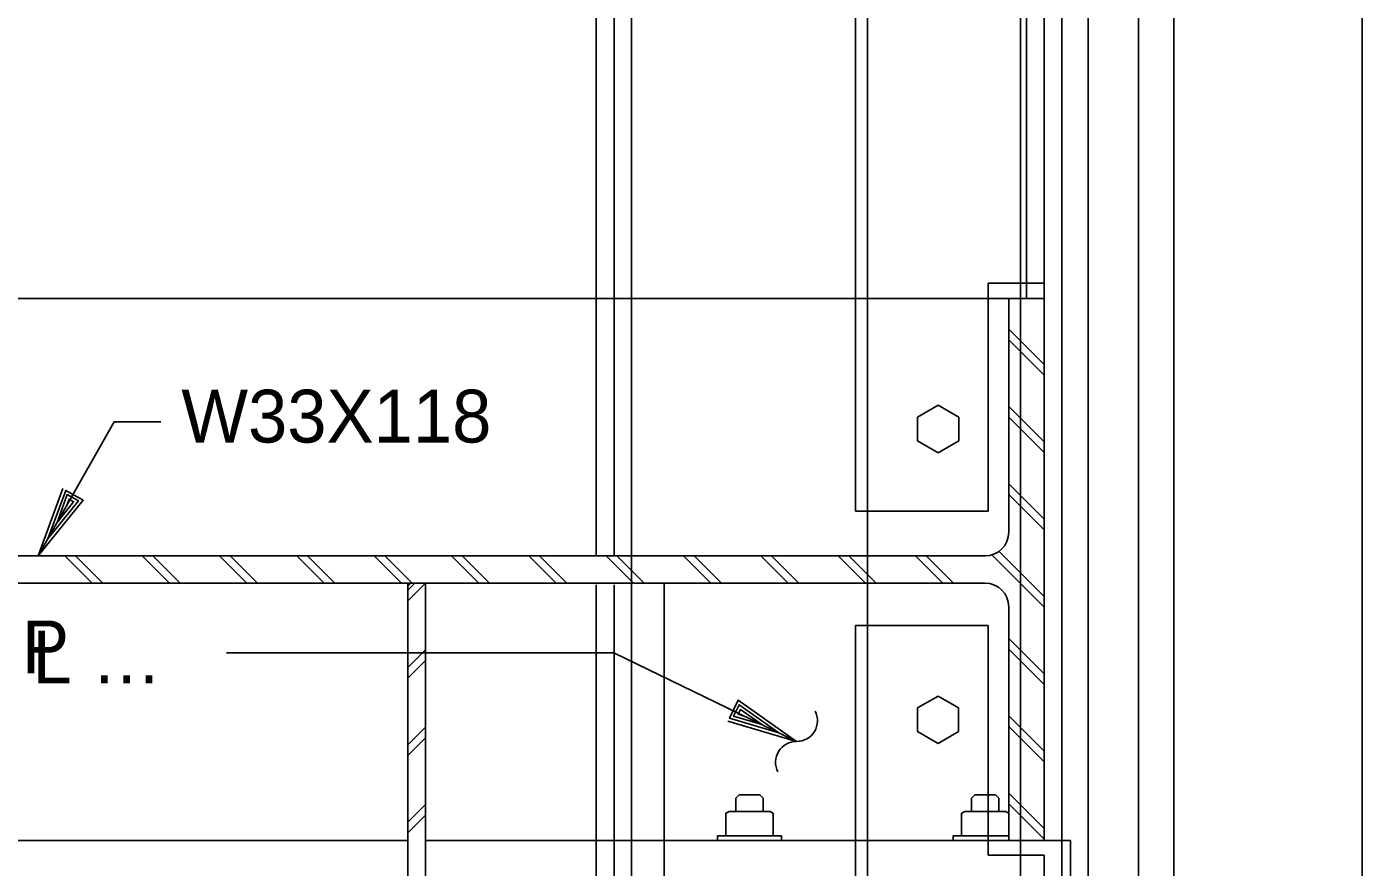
# Model space of a CAD drawing. Extents: x 4.9 to 31.6, y 3.9 to 22.6.
# Drawn here: x 26.163 to 28.524, y 16.518 to 18.004 of the extents above; entities that cross this region are included whole.
import ezdxf

# ---------------------------------------------------------------- set-up
doc = ezdxf.new("R2010")
doc.units = 0
for name, color, linetype in [('Level 2', 7, 'Continuous'), ('Level 25', 7, 'Continuous'), ('Level 3', 7, 'Continuous'), ('Level 44', 7, 'Continuous'), ('Level 50', 7, 'Continuous')]:
    doc.layers.add(name, color=color, linetype=linetype)

msp = doc.modelspace()

# ---------------------------------------------------------------- linework, layer by layer
at = {"layer": 'Level 2'}
for p, q in [((27.9927, 21.2634), (27.9927, 16.5655)), ((28.0395, 21.2634), (28.0395, 15.6699)), ((27.1697, 17.5238), (27.1697, 20.9561)), ((27.201, 17.5238), (27.201, 20.9561)), ((27.2319, 15.7584), (27.2319, 20.9561)), ((27.6281, 17.1475), (27.6281, 20.9561)), ((27.9197, 15.781), (27.9197, 20.6801)), ((27.9302, 17.5238), (27.9302, 20.6801)), ((27.9614, 17.5238), (27.9614, 20.6801)), ((27.9614, 17.5504), (27.8626, 17.5504)), ((27.8626, 17.1475), (27.8626, 17.5504)), ((27.8885, 17.5238), (25.9927, 17.5238)), ((27.1697, 17.0688), (27.1697, 17.5238)), ((27.201, 17.0688), (27.201, 17.5238)), ((27.9614, 17.5238), (27.8885, 17.5238)), ((27.8989, 17.1105), (27.8989, 17.5238)), ((27.9614, 16.5655), (27.9614, 17.5238)), ((27.9614, 17.4071), (27.8989, 17.4696)), ((27.9614, 17.3883), (27.8989, 17.4508)), ((27.7741, 17.3348), (27.7377, 17.3138)), ((27.7741, 17.3348), (27.8104, 17.3138)), ((27.9614, 17.2704), (27.8989, 17.3329)), ((27.7377, 17.3138), (27.7377, 17.272)), ((27.8104, 17.3138), (27.8104, 17.272)), ((27.9614, 17.2516), (27.8989, 17.3141)), ((27.7741, 17.251), (27.7377, 17.272)), ((27.7741, 17.251), (27.8104, 17.272)), ((27.9614, 17.1337), (27.8989, 17.1962)), ((27.9614, 17.1149), (27.8989, 17.1774)), ((27.8626, 17.1475), (27.6281, 17.1475)), ((27.9614, 16.997), (27.8817, 17.0767)), ((25.326, 17.0688), (26.4145, 17.0688)), ((26.2786, 17.0205), (26.2303, 17.0688)), ((26.2974, 17.0205), (26.2491, 17.0688)), ((26.4153, 17.0205), (26.367, 17.0688)), ((26.4342, 17.0205), (26.3858, 17.0688)), ((27.8572, 17.0688), (26.4145, 17.0688)), ((26.552, 17.0205), (26.5037, 17.0688)), ((26.5709, 17.0205), (26.5225, 17.0688)), ((26.6887, 17.0205), (26.6404, 17.0688)), ((26.7076, 17.0205), (26.6592, 17.0688)), ((26.8254, 17.0205), (26.7771, 17.0688)), ((26.8443, 17.0205), (26.7959, 17.0688)), ((26.9621, 17.0205), (26.9138, 17.0688)), ((26.981, 17.0205), (26.9327, 17.0688)), ((27.0988, 17.0205), (27.0505, 17.0688)), ((27.1177, 17.0205), (27.0694, 17.0688)), ((27.2356, 17.0205), (27.1872, 17.0688)), ((27.2544, 17.0205), (27.2061, 17.0688)), ((27.3723, 17.0205), (27.3239, 17.0688)), ((27.3911, 17.0205), (27.3428, 17.0688)), ((27.509, 17.0205), (27.4606, 17.0688)), ((27.5278, 17.0205), (27.4795, 17.0688)), ((27.6457, 17.0205), (27.5973, 17.0688)), ((27.6645, 17.0205), (27.6162, 17.0688)), ((27.7824, 17.0205), (27.7341, 17.0688)), ((27.8012, 17.0205), (27.7529, 17.0688)), ((27.9614, 16.9781), (27.869, 17.0705)), ((25.326, 17.0205), (26.4145, 17.0205)), ((27.8572, 17.0205), (26.4145, 17.0205)), ((26.8364, 15.7168), (26.8364, 17.0205)), ((26.8677, 15.7168), (26.8677, 17.0205)), ((27.1697, 16.5655), (27.1697, 17.0176)), ((27.201, 16.5655), (27.201, 17.0176)), ((27.8989, 16.5655), (27.8989, 16.9788)), ((27.8626, 16.9459), (27.6281, 16.9459)), ((27.6281, 15.781), (27.6281, 16.9459)), ((27.8626, 16.9459), (27.8626, 16.5398)), ((27.9614, 16.8603), (27.8989, 16.9228)), ((27.9614, 16.8415), (27.8989, 16.904)), ((27.7738, 16.8211), (27.7374, 16.8001)), ((27.7738, 16.8211), (27.8101, 16.8001)), ((27.7374, 16.8001), (27.7374, 16.7583)), ((27.8101, 16.8001), (27.8101, 16.7583)), ((27.9614, 16.7236), (27.8989, 16.7861)), ((27.9614, 16.7048), (27.8989, 16.7673)), ((27.7738, 16.7373), (27.7374, 16.7583)), ((27.7738, 16.7373), (27.8101, 16.7583)), ((27.9614, 16.5869), (27.8989, 16.6494)), ((27.4163, 16.6406), (27.4224, 16.6467)), ((27.4163, 16.6406), (27.4163, 16.6172)), ((27.4224, 16.6467), (27.4587, 16.6467)), ((27.4648, 16.6406), (27.4587, 16.6467)), ((27.4648, 16.6406), (27.4648, 16.6172)), ((27.833, 16.6406), (27.839, 16.6467)), ((27.833, 16.6406), (27.833, 16.6172)), ((27.8754, 16.6467), (27.839, 16.6467)), ((27.8815, 16.6406), (27.8754, 16.6467)), ((27.8815, 16.6406), (27.8815, 16.6172)), ((27.9614, 16.5681), (27.8989, 16.6306)), ((27.4043, 16.6172), (27.3987, 16.614)), ((27.3987, 16.5742), (27.3987, 16.614)), ((27.4043, 16.6172), (27.4768, 16.6172)), ((27.4768, 16.6172), (27.4824, 16.614)), ((27.4824, 16.5742), (27.4824, 16.614)), ((27.821, 16.6172), (27.8154, 16.614)), ((27.8154, 16.5742), (27.8154, 16.614)), ((27.8934, 16.6172), (27.821, 16.6172)), ((27.8934, 16.6172), (27.8991, 16.614)), ((24.8729, 16.5655), (26.4145, 16.5655)), ((26.4145, 16.5655), (26.8364, 16.5655)), ((28.0083, 16.5655), (26.8677, 16.5655)), ((27.1697, 15.748), (27.1697, 16.5655)), ((27.201, 15.7168), (27.201, 16.5655)), ((27.3839, 16.5742), (27.4972, 16.5742)), ((27.3839, 16.5655), (27.3839, 16.5742)), ((27.3987, 16.5742), (27.4824, 16.5742)), ((27.4199, 16.5742), (27.3987, 16.5742)), ((27.4972, 16.5655), (27.4972, 16.5742)), ((27.8005, 16.5655), (27.8005, 16.5742)), ((27.8989, 16.5742), (27.8005, 16.5742)), ((27.8885, 16.5742), (27.8154, 16.5742)), ((27.9927, 16.5655), (27.9927, 16.4821)), ((27.9614, 16.5398), (27.8626, 16.5398))]:
    msp.add_line(p, q, dxfattribs=at)
for centre, start, end in [((27.8572, 17.1105), 270, 360), ((27.8572, 16.9788), 0, 90)]:
    msp.add_arc(centre, 0.0417, start, end, dxfattribs=at)
at = {"layer": 'Level 3'}
for p, q in [((26.8364, 17.0153), (26.8416, 17.0205)), ((26.8364, 17.0083), (26.8486, 17.0205)), ((26.8364, 16.9895), (26.8674, 17.0205)), ((26.8364, 16.8716), (26.8677, 16.9029)), ((26.8364, 16.8528), (26.8677, 16.884)), ((26.8364, 16.7349), (26.8677, 16.7661)), ((26.8364, 16.7161), (26.8677, 16.7473)), ((26.8364, 16.5982), (26.8677, 16.6294)), ((26.8364, 16.5794), (26.8677, 16.6106))]:
    msp.add_line(p, q, dxfattribs=at)
for points in [[(26.3995, 17.3055), (26.3171, 17.3055), (26.1831, 17.0688)], [(26.5156, 16.8975), (27.2009, 16.8975), (27.5236, 16.7409)]]:
    msp.add_lwpolyline(points, dxfattribs=at)
at = {"layer": 'Level 44'}
for centre, start, end in [((27.5239, 16.7776), 269.5981, 27.4773), ((27.5234, 16.7041), 89.5981, 207.4773)]:
    msp.add_arc(centre, 0.0368, start, end, dxfattribs=at)
at = {"layer": 'Level 50'}
for p, q in [((28.1281, 21.2634), (28.1281, 15.4926)), ((28.1906, 21.2634), (28.1906, 15.4926)), ((28.5239, 21.2634), (28.5239, 16.0933)), ((27.6489, 20.9561), (27.6489, 13.8527)), ((26.2002, 17.099), (26.2002, 17.099)), ((26.1831, 17.0688), (26.1831, 17.0688)), ((27.2895, 16.4821), (27.2895, 17.0205)), ((27.4924, 16.756), (27.4924, 16.756)), ((27.5236, 16.7409), (27.5236, 16.7409)), ((28.0083, 16.4821), (28.0083, 16.5655)), ((27.9614, 16.5398), (27.9614, 16.4821))]:
    msp.add_line(p, q, dxfattribs=at)
for points in [[(26.2265, 17.1875), (26.1831, 17.0688), (26.2625, 17.1671), (26.2318, 17.1845), (26.2002, 17.099), (26.2541, 17.1658), (26.2344, 17.1769), (26.2166, 17.128), (26.2456, 17.1644), (26.2375, 17.169), (26.2337, 17.1582)], [(27.4024, 16.7767), (27.5236, 16.7409), (27.4205, 16.8139), (27.4051, 16.7821), (27.4924, 16.756), (27.4224, 16.8056), (27.4125, 16.7852), (27.4624, 16.7705), (27.4243, 16.7972), (27.4202, 16.7888), (27.4313, 16.7857)]]:
    msp.add_lwpolyline(points, dxfattribs=at)

# ---------------------------------------------------------------- texts
at = {"layer": 'Level 25'}
for s, height, p in [('W33X118', 0.09333, (26.4361, 17.269)), ('P', 0.0933, (26.1543, 16.8612)), ('L …', 0.09333, (26.1728, 16.8433))]:
    msp.add_text(s, height=height, dxfattribs=at).set_placement(p)

doc.saveas('drawing.dxf')
